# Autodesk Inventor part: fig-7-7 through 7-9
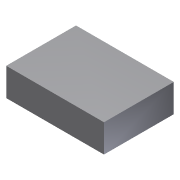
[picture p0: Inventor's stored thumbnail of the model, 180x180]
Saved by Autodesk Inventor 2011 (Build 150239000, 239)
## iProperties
Created: 2009-09
Part Number: fig-7-7 through 7-9
Document SubType Name: Modeling
Designer: Sham
Density: 1 g/cm^3
Author: Sham
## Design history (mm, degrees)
sketch "Sketch1"
  geometry: L1 (-28, 20)-(0, 20); L2 (0, 20)-(0, 0); L3 (0, 0)-(-28, 0); L4 (-28, 0)-(-28, 20)
  constraints: 8 end point, 2 parallel, 1 horizontal, 1 perpendicular
extrude "Extrusion1" new body sketch "Sketch1" distance "d0" = 8; taper "d1" = 0 deg
body "Solid1"
